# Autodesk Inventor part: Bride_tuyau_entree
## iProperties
Shininess: 64.0
Length Units: 11269
Angle Units: 11279
Time Units: 11290
Mass Units: 11283
Length Display Precision: 3
Angle Display Precision: 2
Compacted: True
Part Number: Bride_tuyau_entree
Document SubType Name: Modeling
Created: 2008-02
Material: Par défaut
Designer: Pascal
Density: 0.0
Volumn: 0.0
Area: 0.0
PropertySet Name: Model Information
Control State: 0
Master: False
Checked Out: False
DESIGNATION: Ligne tuyauterie entrée
Author: Pascal
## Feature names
1. Extrusion1
2. Extrusion2
3. Réseau circulaire1 [Circular Pattern]
4. Révolution1 [Revolution]
5. Balayage1
